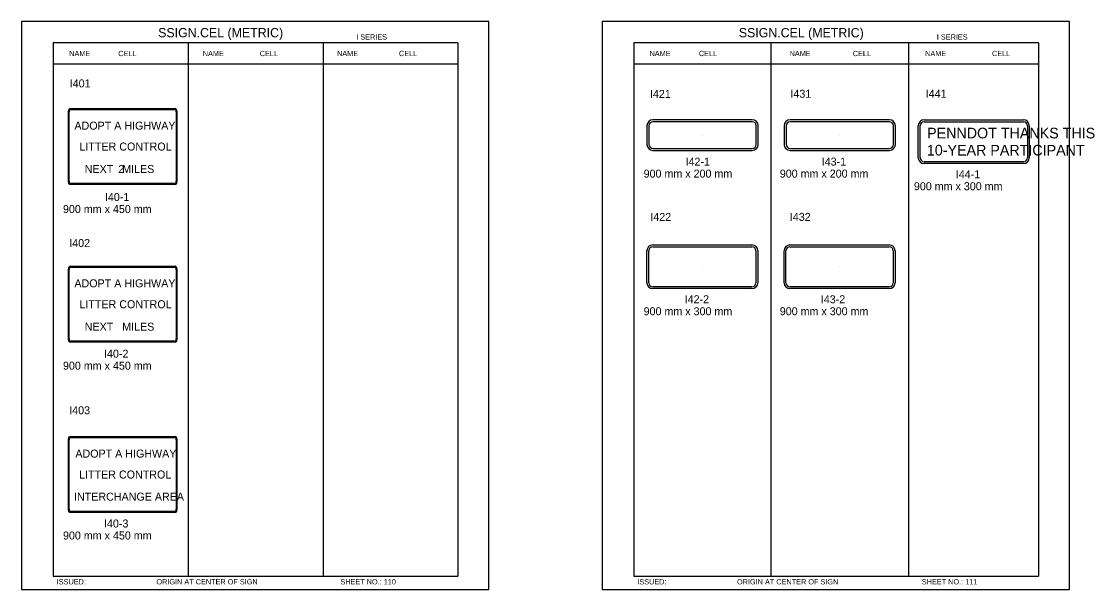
# Model space of a CAD drawing. Extents: x -12 to 6962, y -3756 to 679.
# Drawn here: x 4896.5 to 5298.8, y -696.1 to -483 of the extents above; entities that cross this region are included whole.
import ezdxf

# ---------------------------------------------------------------- set-up
doc = ezdxf.new("R2010")
doc.units = 0
for name, color, linetype in [('Level 1', 7, 'Continuous'), ('Level 2', 7, 'Continuous'), ('Level 3', 7, 'Continuous'), ('Level 61', 7, 'Continuous')]:
    doc.layers.add(name, color=color, linetype=linetype)

msp = doc.modelspace()

# ---------------------------------------------------------------- linework, layer by layer
at = {"layer": 'Level 1'}
for p, q in [((5060.12, -491.06), (4908.37, -491.06)), ((4908.37, -491.06), (4908.37, -691.06)), ((4958.95, -491.06), (4958.95, -691.06)), ((5009.54, -491.06), (5009.54, -691.06)), ((5060.12, -491.06), (5060.12, -691.06)), ((5277.79, -491.06), (5126.03, -491.06)), ((5126.03, -491.06), (5126.03, -691.06)), ((5177.48, -491.06), (5177.48, -691.06)), ((5229.1, -491.06), (5229.1, -691.06)), ((5277.79, -491.06), (5277.79, -691.06)), ((5060.12, -498.98), (4908.37, -498.98)), ((5277.79, -498.98), (5126.03, -498.98)), ((4914.08, -543.21), (4914.08, -516.66)), ((4914.33, -542.93), (4914.33, -516.94)), ((4914.76, -515.71), (4954.11, -515.71)), ((4914.96, -516.06), (4953.91, -516.06)), ((4954.53, -516.94), (4954.53, -542.93)), ((4954.79, -516.66), (4954.79, -543.21)), ((5131, -522.13), (5131, -529.13)), ((5131.75, -522.13), (5131.75, -529.13)), ((5170.45, -519.88), (5133.25, -519.88)), ((5170.45, -520.63), (5133.25, -520.63)), ((5171.95, -529.13), (5171.95, -522.13)), ((5172.7, -529.13), (5172.7, -522.13)), ((5182.44, -522.13), (5182.44, -529.13)), ((5183.19, -522.13), (5183.19, -529.13)), ((5221.89, -519.88), (5184.69, -519.88)), ((5221.89, -520.63), (5184.69, -520.63)), ((5223.39, -529.13), (5223.39, -522.13)), ((5224.14, -529.13), (5224.14, -522.13)), ((5232.73, -534.13), (5232.73, -522.13)), ((5233.43, -534.13), (5233.43, -522.13)), ((5234.93, -519.93), (5272.14, -519.93)), ((5234.93, -520.63), (5272.14, -520.63)), ((5273.64, -522.13), (5273.64, -534.13)), ((5274.34, -522.13), (5274.34, -534.13)), ((5151.81, -525.69), (5151.81, -525.69)), ((5203.25, -525.69), (5203.25, -525.69)), ((4934.43, -529.94), (4934.43, -529.94)), ((5133.25, -530.63), (5170.45, -530.63)), ((5184.69, -530.63), (5221.89, -530.63)), ((5253.53, -528.13), (5253.53, -528.13)), ((5133.25, -531.38), (5170.45, -531.38)), ((5184.69, -531.38), (5221.89, -531.38)), ((5272.14, -535.63), (5234.93, -535.63)), ((5272.14, -536.33), (5234.93, -536.33)), ((4954.11, -544.16), (4914.76, -544.16)), ((4953.91, -543.81), (4914.96, -543.81)), ((5133.16, -566.83), (5170.36, -566.83)), ((5184.6, -566.83), (5221.81, -566.83)), ((5130.96, -581.03), (5130.96, -569.03)), ((5131.66, -581.03), (5131.66, -569.03)), ((5133.16, -567.53), (5170.36, -567.53)), ((5171.86, -569.03), (5171.86, -581.03)), ((5172.56, -569.03), (5172.56, -581.03)), ((5182.4, -581.03), (5182.4, -569.03)), ((5183.1, -581.03), (5183.1, -569.03)), ((5184.6, -567.53), (5221.81, -567.53)), ((5223.31, -569.03), (5223.31, -581.03)), ((5224.01, -569.03), (5224.01, -581.03)), ((4914.76, -574.86), (4954.11, -574.86)), ((4914.96, -575.21), (4953.91, -575.21)), ((5151.76, -575.04), (5151.76, -575.04)), ((5203.21, -575.04), (5203.21, -575.04)), ((4914.08, -602.36), (4914.08, -575.81)), ((4914.33, -602.08), (4914.33, -576.09)), ((4954.53, -576.09), (4954.53, -602.08)), ((4954.79, -575.81), (4954.79, -602.36)), ((5170.36, -582.53), (5133.16, -582.53)), ((5170.36, -583.23), (5133.16, -583.23)), ((5221.81, -582.53), (5184.6, -582.53)), ((5221.81, -583.23), (5184.6, -583.23)), ((4934.43, -589.08), (4934.43, -589.08)), ((4954.11, -603.31), (4914.76, -603.31)), ((4953.91, -602.96), (4914.96, -602.96)), ((4914.76, -638.73), (4954.11, -638.73)), ((4914.96, -639.08), (4953.91, -639.08)), ((4914.08, -666.23), (4914.08, -639.68)), ((4914.33, -665.95), (4914.33, -639.96)), ((4954.53, -639.96), (4954.53, -665.95)), ((4954.79, -639.68), (4954.79, -666.23)), ((4934.43, -652.96), (4934.43, -652.96)), ((4954.11, -667.18), (4914.76, -667.18)), ((4953.91, -666.83), (4914.96, -666.83)), ((4908.37, -691.06), (5060.12, -691.06)), ((5126.03, -691.06), (5277.79, -691.06))]:
    msp.add_line(p, q, dxfattribs=at)
for centre, radius, start, end in [((5133.25, -522.13), 2.25, 90, 180), ((5133.25, -522.13), 1.5, 90, 180), ((5170.45, -522.13), 2.25, 0, 90), ((5170.45, -522.13), 1.5, 0, 90), ((5184.69, -522.13), 2.25, 90, 180), ((5184.69, -522.13), 1.5, 90, 180), ((5221.89, -522.13), 2.25, 0, 90), ((5221.89, -522.13), 1.5, 0, 90), ((5234.93, -522.13), 2.2, 90, 180), ((5234.93, -522.13), 1.5, 90, 180), ((5272.14, -522.13), 2.2, 0, 90), ((5272.14, -522.13), 1.5, 0, 90), ((5133.25, -529.13), 2.25, 180, 270), ((5133.25, -529.13), 1.5, 180, 270), ((5170.45, -529.13), 1.5, 270, 0), ((5170.45, -529.13), 2.25, 270, 0), ((5184.69, -529.13), 2.25, 180, 270), ((5184.69, -529.13), 1.5, 180, 270), ((5221.89, -529.13), 1.5, 270, 0), ((5221.89, -529.13), 2.25, 270, 0), ((5234.93, -534.13), 2.2, 180, 270), ((5234.93, -534.13), 1.5, 180, 270), ((5272.14, -534.13), 1.5, 270, 0), ((5272.14, -534.13), 2.2, 270, 0), ((5133.16, -569.03), 2.2, 90, 180), ((5170.36, -569.03), 2.2, 0, 90), ((5184.6, -569.03), 2.2, 90, 180), ((5221.81, -569.03), 2.2, 0, 90), ((5133.16, -569.03), 1.5, 90, 180), ((5170.36, -569.03), 1.5, 0, 90), ((5184.6, -569.03), 1.5, 90, 180), ((5221.81, -569.03), 1.5, 0, 90), ((5133.16, -581.03), 2.2, 180, 270), ((5133.16, -581.03), 1.5, 180, 270), ((5170.36, -581.03), 1.5, 270, 0), ((5170.36, -581.03), 2.2, 270, 0), ((5184.6, -581.03), 2.2, 180, 270), ((5184.6, -581.03), 1.5, 180, 270), ((5221.81, -581.03), 1.5, 270, 0), ((5221.81, -581.03), 2.2, 270, 0)]:
    msp.add_arc(centre, radius, start, end, dxfattribs=at)
for centre, major_axis, start_param, end_param in [((4914.76, -516.66), (0, -0.948), 3.141593, 4.712389), ((4914.96, -516.94), (0, 0.877), 0, 1.570796), ((4953.91, -516.94), (0, 0.877), 4.712389, 6.283185), ((4954.11, -516.66), (0, 0.948), 4.712389, 6.283185), ((4914.96, -542.93), (0, -0.877), 4.712389, 6.283185), ((4953.91, -542.93), (0, 0.877), 3.141593, 4.712389), ((4914.76, -543.21), (0, -0.948), 4.712389, 6.283185), ((4954.11, -543.21), (0, 0.948), 3.141593, 4.712389), ((4914.76, -575.81), (0, -0.948), 3.141593, 4.712389), ((4914.96, -576.09), (0, 0.877), 0, 1.570796), ((4953.91, -576.09), (0, 0.877), 4.712389, 6.283185), ((4954.11, -575.81), (0, 0.948), 4.712389, 6.283185), ((4914.76, -602.36), (0, -0.948), 4.712389, 6.283185), ((4914.96, -602.08), (0, -0.877), 4.712389, 6.283185), ((4953.91, -602.08), (0, 0.877), 3.141593, 4.712389), ((4954.11, -602.36), (0, 0.948), 3.141593, 4.712389), ((4914.76, -639.68), (0, -0.948), 3.141593, 4.712389), ((4914.96, -639.96), (0, 0.877), 0, 1.570796), ((4953.91, -639.96), (0, 0.877), 4.712389, 6.283185), ((4954.11, -639.68), (0, 0.948), 4.712389, 6.283185), ((4914.76, -666.23), (0, -0.948), 4.712389, 6.283185), ((4914.96, -665.95), (0, -0.877), 4.712389, 6.283185), ((4953.91, -665.95), (0, 0.877), 3.141593, 4.712389), ((4954.11, -666.23), (0, 0.948), 3.141593, 4.712389)]:
    msp.add_ellipse(centre, major_axis=major_axis, ratio=0.715449, start_param=start_param, end_param=end_param, dxfattribs=at)
at = {"layer": 'Level 61'}
for points in [[(4896.49, -696.11), (5071.75, -696.11), (5071.75, -483.01), (4896.49, -483.01)], [(5114.16, -696.11), (5289.42, -696.11), (5289.42, -483.01), (5114.16, -483.01)]]:
    msp.add_lwpolyline(points, close=True, dxfattribs=at)

# ---------------------------------------------------------------- texts
at = {"layer": 'Level 1'}
for s, height, p in [('ADOPT A HIGHWAY', 3, (4916.34, -523.59)), ('PENNDOT THANKS THIS', 4, (5236.03, -526.88)), ('LITTER CONTROL', 3, (4918.23, -531.44)), ('10-YEAR PARTICIPANT', 4, (5235.94, -533.3)), ('NEXT   MILES', 3, (4920.21, -539.86)), ('2', 3, (4932.77, -539.86)), ('ADOPT A HIGHWAY', 3, (4916.33, -582.74)), ('LITTER CONTROL', 3, (4918.23, -590.58)), ('NEXT   MILES', 3, (4920.21, -599.01)), ('ADOPT A HIGHWAY', 3, (4916.69, -646.61)), ('LITTER CONTROL', 3, (4918.11, -654.46)), ('INTERCHANGE AREA', 3, (4916.19, -662.76))]:
    msp.add_text(s, height=height, dxfattribs=at).set_placement(p)
at = {"layer": 'Level 2'}
for s, p in [('I401', (4914.6, -507.74)), ('I421', (5132.11, -511.7)), ('I431', (5184.78, -511.63)), ('I441', (5235.48, -511.63)), ('I422', (5132.26, -557.84)), ('I432', (5184.56, -557.82)), ('I402', (4914.4, -567.63)), ('I403', (4914.39, -630.36))]:
    msp.add_text(s, height=3, dxfattribs=at).set_placement(p)
at = {"layer": 'Level 3'}
for s, height, p in [('SSIGN.CEL (METRIC)', 3.4642, (4947.75, -488.95)), ('SSIGN.CEL (METRIC)', 3.4642, (5165.42, -488.95)), ('I SERIES', 1.979, (5022, -489.82)), ('I SERIES', 1.979, (5239.66, -489.82)), ('NAME', 1.98, (4914.39, -496.02)), ('CELL', 1.98, (4932.8, -496.02)), ('NAME', 1.98, (4964.47, -496.02)), ('CELL', 1.98, (4985.82, -496.02)), ('NAME', 1.98, (5014.81, -496.02)), ('CELL', 1.98, (5038.02, -496.02)), ('NAME', 1.98, (5131.95, -496.02)), ('CELL', 1.98, (5150.47, -496.02)), ('NAME', 1.98, (5184.46, -496.02)), ('CELL', 1.98, (5208.15, -496.02)), ('NAME', 1.98, (5235.29, -496.02)), ('CELL', 1.98, (5260.36, -496.02)), ('I42-1', 3, (5145.47, -537.09)), ('I43-1', 3, (5196.51, -537.09)), ('900 mm x 200 mm', 3, (5129.75, -541.59)), ('900 mm x 200 mm', 3, (5180.79, -541.59)), ('I44-1', 3, (5246.79, -541.82)), ('900 mm x 300 mm', 3, (5231.07, -546.32)), ('I40-1', 3, (4927.78, -550.37)), ('900 mm x 450 mm', 3, (4912.06, -554.87)), ('I42-2', 3, (5145.13, -588.72)), ('I43-2', 3, (5196.17, -588.72)), ('900 mm x 300 mm', 3, (5129.75, -593.22)), ('900 mm x 300 mm', 3, (5180.79, -593.22)), ('I40-2', 3, (4927.44, -609.13)), ('900 mm x 450 mm', 3, (4912.06, -613.63)), ('I40-3', 3, (4927.44, -672.83)), ('900 mm x 450 mm', 3, (4912.06, -677.33)), ('ISSUED:', 1.98, (4909.71, -694.18)), ('ORIGIN AT CENTER OF SIGN', 1.9795, (4947.09, -694.18)), ('SHEET NO.: 110', 1.9795, (5016.06, -694.18)), ('ISSUED:', 1.98, (5127.38, -694.18)), ('ORIGIN AT CENTER OF SIGN', 1.9795, (5164.76, -694.18)), ('SHEET NO.: 111', 1.9795, (5234.04, -694.18))]:
    msp.add_text(s, height=height, dxfattribs=at).set_placement(p)

doc.saveas('drawing.dxf')
